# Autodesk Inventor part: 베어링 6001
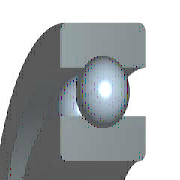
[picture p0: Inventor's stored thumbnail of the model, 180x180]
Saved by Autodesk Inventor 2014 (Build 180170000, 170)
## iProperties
IsCustomPart: 0
Created: 2015-10
Part Number: 베어링 6001
Material: 강, 연강
Description: 깊은 그루브 볼 베어링
Document SubType Name: Modeling
Standard: KS B 2023
Designer: mdu
Standards Organization: KS
Language: ko-KR
Size Designation: 6001 - 12 x 28 x 8
Categories: <MemberInstance><Categories><Category DisplayName="샤프트 부품" InternalName="7f7aeb1f-a693-4053-b835-cee3144e0d98" Mnemonic="SHFT"><Category DisplayName="베어링" Inter
Density: 1 g/cm^3
Appearance: 강철
Author: mdu
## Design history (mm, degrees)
sketch "스케치" dims "d0" = 4.16 (= -0.26 x WD + 0.26 x BD)
  geometry: L1 (1.92, 10)-(6.08, 10); L2 (4, 10)-(4, 7.92); L3 (4, 10)-(4, 12.08); L4 (2.454, 8.608)-(0, 8.608); L5 (0, 6)-(8, 6); L6 (2.454, 11.392)-(0, 11.392); L7 (0, 14)-(8, 14); L8 (8, 6)-(8, 8.608); L9 (5.546, 8.608)-(8, 8.608); L10 (5.546, 11.392)-(8, 11.392); L11 (8, 14)-(8, 11.392); L12 (-1.4, 0)-(8.4, 0) reference; L13 (0, -0.3)-(0, 5.3) reference
  constraints: 22 end point, 4 point on line, 2 collinear, 2 perpendicular, 2 symmetric about line, 1 midpoint, 1 parallel, 14 other
  dimensions: "d9" = 12 diameter of L5 L12 (= WD); "d11" = 28 diameter of L7 L12 (= BD); "d12" = 8 distance between parallel lines of L8 L13 (= KB); "d13" = 17.216 diameter of L9 L12 (= 0.326 x BD + 0.674 x WD)
revolve "본체" stored, may be unused: angle "d6" = 90 deg
revolve "볼" stored, may be unused: angle "d7" = 90 deg
pattern_circular "IDS_ARRAYBALL[SIMPL:T]" dims angle "d3" = 360 deg
body "Solid1"
fillet "모깎기1" dims "d1" = 0.3 (= KRS)
other parameters: "WD" = 12 [user parameter; used in 5 equation terms], "BD" = 28 [user parameter; used in 5 equation terms], "KB" = 8 [user parameter; used in 1 equation term], "KRS" = 0.3 [user parameter; used in 1 equation term], "d4" = 0, "d5" = 0, "d8" = 0, "d14" = 0, "d15" = 0, "BBA" = 0 [user parameter], "BC0" = 2360000 [user parameter], "BC" = 5070000 [user parameter], "BR" = 14 (= 0.5 x BD) [user parameter], "WR" = 6 (= 0.5 x WD) [user parameter]
